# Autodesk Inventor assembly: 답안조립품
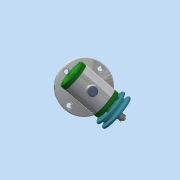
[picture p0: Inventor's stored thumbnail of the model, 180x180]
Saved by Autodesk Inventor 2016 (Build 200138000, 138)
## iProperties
Created: 2018-12
Part Number: 답안조립품
Material: 일반
Document SubType Name: Weldment
Designer: 3sil_cad0123
Weld Material: Welded Aluminum-6061
Author: 3sil_cad0123
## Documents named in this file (15)
- C:\Users\3sil_cad0123\Desktop\481208V1002\답안조립품.iam
- C:\Users\3sil_cad0123\Desktop\481208V1002\V벨트풀리.ipt
- C:\Users\3sil_cad0123\Desktop\481208V1002\고무캡.ipt
- C:\Users\3sil_cad0123\Desktop\481208V1002\너트 M8.ipt
- 너트 M8.ipt
- C:\Users\3sil_cad0123\Desktop\481208V1002\뒤커버.ipt
- C:\Users\3sil_cad0123\Desktop\481208V1002\베어링 15 x 32 x 9.ipt
- C:\Users\3sil_cad0123\Desktop\481208V1002\본체.ipt
- C:\Users\3sil_cad0123\Desktop\481208V1002\볼트 M4 x 12.ipt
- C:\Users\3sil_cad0123\Desktop\481208V1002\스프링와셔 8.ipt
- C:\Users\3sil_cad0123\Desktop\481208V1002\앞커버.ipt
- C:\Users\3sil_cad0123\Desktop\481208V1002\오일 실 15 25 7.ipt
- C:\Users\3sil_cad0123\Desktop\481208V1002\와셔 8x17.ipt
- C:\Users\3sil_cad0123\Desktop\481208V1002\축.ipt
- C:\Users\3sil_cad0123\Desktop\481208V1002\키 3 x 3 x 12.ipt
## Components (2 placed, 2 different names)
1. V벨트풀리:1
2. 고무캡:1
